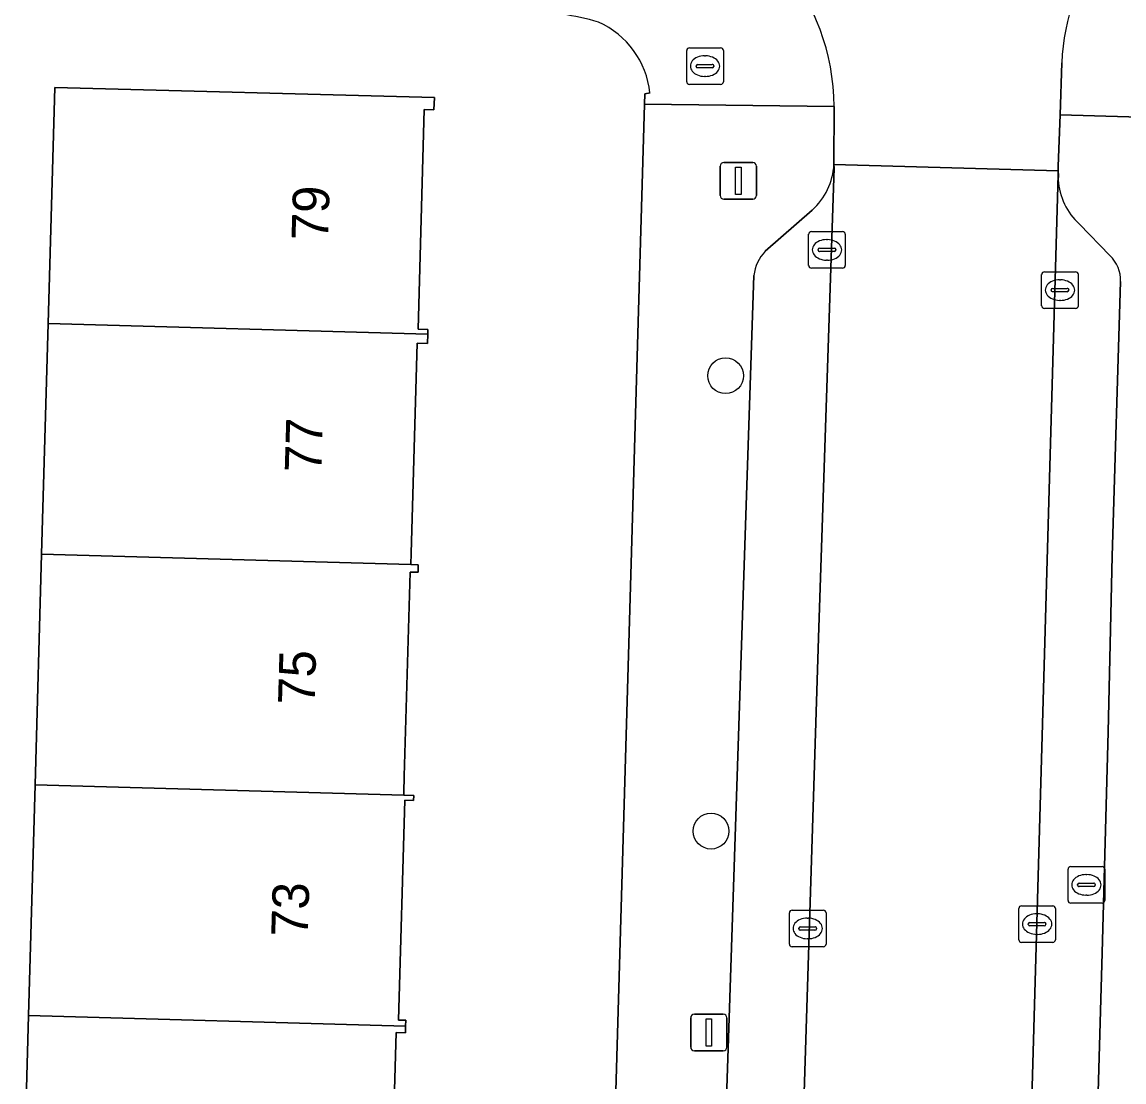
# Model space of a CAD drawing. Extents: x 162082 to 163401, y 388089 to 388636.
# Drawn here: x 162511.82 to 162541.91, y 388427.55 to 388456.49 of the extents above; entities that cross this region are included whole.
import ezdxf

# ---------------------------------------------------------------- set-up
doc = ezdxf.new("R2010")
doc.units = 0
for name, color, linetype in [('IMGEO_Boom', 7, 'Continuous'), ('IMGEO_Brandkraan', 7, 'Continuous'), ('IMGEO_Erf', 7, 'Continuous'), ('IMGEO_Kolk', 7, 'Continuous'), ('IMGEO_Lichtmast', 7, 'Continuous'), ('IMGEO_Pand', 7, 'Continuous'), ('IMGEO_Pand_nummerreeks', 7, 'Continuous'), ('IMGEO_Parkeervlak_open', 7, 'Continuous'), ('IMGEO_Rijbaan_lokaal_gesloten', 7, 'Continuous'), ('IMGEO_Rijbaan_lokaal_open', 7, 'Continuous'), ('IMGEO_Rioolput', 7, 'Continuous'), ('IMGEO_Voetpad_open', 7, 'Continuous')]:
    doc.layers.add(name, color=color, linetype=linetype)

msp = doc.modelspace()

# ---------------------------------------------------------------- linework, layer by layer
at = {"layer": 'IMGEO_Boom'}
for centre in [(162531.033, 388446.831), (162530.634, 388434.396)]:
    msp.add_circle(centre, 0.489, dxfattribs=at)
at = {"layer": 'IMGEO_Brandkraan'}
for p, q in [((162529.97, 388454.857), (162529.97, 388455.709)), ((162530.045, 388455.783), (162530.897, 388455.783)), ((162530.971, 388455.709), (162530.971, 388454.857)), ((162530.458, 388455.563), (162530.483, 388455.563)), ((162530.229, 388455.277), (162530.229, 388455.289)), ((162530.667, 388455.24), (162530.269, 388455.24)), ((162530.272, 388455.326), (162530.67, 388455.326)), ((162530.713, 388455.289), (162530.713, 388455.277)), ((162530.481, 388455.003), (162530.456, 388455.003)), ((162530.897, 388454.783), (162530.045, 388454.783))]:
    msp.add_line(p, q, dxfattribs=at)
for points in [[(162529.97, 388454.857), (162529.97, 388455.709)], [(162530.045, 388455.783), (162530.897, 388455.783)], [(162530.971, 388455.709), (162530.971, 388454.857)], [(162530.897, 388454.783), (162530.045, 388454.783)]]:
    msp.add_lwpolyline(points, dxfattribs=at)
for centre, radius, start, end in [((162530.047, 388455.707), 0.0765, 91.552, 178.448), ((162530.047, 388455.707), 0.0765, 91.552, 178.448), ((162530.895, 388455.707), 0.0765, 1.552, 88.448), ((162530.895, 388455.707), 0.0765, 1.552, 88.448), ((162530.269, 388455.286), 0.0403, 85.8775, 175.7526), ((162530.266, 388455.276), 0.0366, 178.938, 274.7102), ((162530.67, 388455.283), 0.043, 264.8664, 352.4533), ((162530.674, 388455.288), 0.0386, 1.7309, 96.639), ((162530.047, 388454.859), 0.0765, 181.552, 268.448), ((162530.047, 388454.859), 0.0765, 181.552, 268.448), ((162530.895, 388454.859), 0.0765, 271.552, 358.448), ((162530.895, 388454.859), 0.0765, 271.552, 358.448)]:
    msp.add_arc(centre, radius, start, end, dxfattribs=at)
for centre, major_axis, ratio, start_param, end_param in [((162530.457, 388455.283), (-0.387, 0.002), 0.722429, 4.712389, 7.853982), ((162530.482, 388455.283), (-0.39, 0.002), 0.717154, 1.570796, 4.712389)]:
    msp.add_ellipse(centre, major_axis=major_axis, ratio=ratio, start_param=start_param, end_param=end_param, dxfattribs=at)
at = {"layer": 'IMGEO_Erf'}
for points in [[(162511.823, 388423.065), (162512.001, 388429.364), (162512.178, 388435.661), (162512.356, 388441.959), (162512.534, 388448.256), (162512.716, 388454.703), (162523.081, 388454.43), (162523.067, 388454.092), (162522.804, 388454.1), (162522.635, 388448.098), (162522.906, 388448.091), (162522.902, 388447.964), (162522.895, 388447.711), (162522.612, 388447.719), (162522.449, 388441.984), (162522.44, 388441.675), (162522.641, 388441.669), (162522.635, 388441.462), (162522.417, 388441.468), (162522.26, 388435.898), (162522.247, 388435.449), (162522.245, 388435.378), (162522.519, 388435.37), (162522.515, 388435.233), (162522.27, 388435.24), (162522.101, 388429.237), (162522.301, 388429.232), (162522.297, 388429.074), (162522.292, 388428.886), (162522.034, 388428.894), (162521.865, 388422.918)], [(162527.34, 388403.481), (162528.815, 388454.241), (162528.823, 388454.524), (162528.969, 388454.551)]]:
    msp.add_lwpolyline(points, dxfattribs=at)
for centre, radius, start, end in [((162525.484, 388449.188), 7.589, 74.1247, 89.3819), ((162526.569, 388454.285), 2.414, 6.3175, 65.776)]:
    msp.add_arc(centre, radius, start, end, dxfattribs=at)
at = {"layer": 'IMGEO_Kolk'}
for p, q in [((162533.3, 388449.84), (162533.3, 388450.692)), ((162533.375, 388450.766), (162534.227, 388450.766)), ((162534.301, 388450.692), (162534.301, 388449.84)), ((162533.602, 388450.309), (162534, 388450.309)), ((162533.788, 388450.546), (162533.813, 388450.546)), ((162533.559, 388450.26), (162533.559, 388450.272)), ((162533.997, 388450.223), (162533.599, 388450.223)), ((162533.811, 388449.986), (162533.786, 388449.986)), ((162534.043, 388450.272), (162534.043, 388450.26)), ((162534.227, 388449.766), (162533.375, 388449.766)), ((162539.662, 388448.742), (162539.662, 388449.594)), ((162539.737, 388449.668), (162540.589, 388449.668)), ((162540.15, 388449.448), (162540.175, 388449.448)), ((162540.663, 388449.594), (162540.663, 388448.742)), ((162539.921, 388449.162), (162539.921, 388449.174)), ((162540.359, 388449.125), (162539.961, 388449.125)), ((162539.964, 388449.211), (162540.362, 388449.211)), ((162540.405, 388449.174), (162540.405, 388449.162)), ((162540.173, 388448.888), (162540.148, 388448.888)), ((162540.589, 388448.668), (162539.737, 388448.668)), ((162532.849, 388432.238), (162533.701, 388432.238)), ((162539.037, 388431.431), (162539.037, 388432.283)), ((162539.112, 388432.357), (162539.964, 388432.357)), ((162540.038, 388432.283), (162540.038, 388431.431)), ((162532.774, 388431.312), (162532.774, 388432.164)), ((162533.262, 388432.018), (162533.287, 388432.018)), ((162533.775, 388432.164), (162533.775, 388431.312)), ((162539.525, 388432.137), (162539.55, 388432.137)), ((162533.033, 388431.732), (162533.033, 388431.744)), ((162533.471, 388431.695), (162533.073, 388431.695)), ((162533.076, 388431.781), (162533.474, 388431.781)), ((162533.517, 388431.744), (162533.517, 388431.732)), ((162539.296, 388431.851), (162539.296, 388431.863)), ((162539.734, 388431.814), (162539.336, 388431.814)), ((162539.339, 388431.9), (162539.737, 388431.9)), ((162539.78, 388431.863), (162539.78, 388431.851)), ((162533.285, 388431.458), (162533.26, 388431.458)), ((162539.964, 388431.357), (162539.112, 388431.357)), ((162539.548, 388431.577), (162539.523, 388431.577)), ((162533.701, 388431.238), (162532.849, 388431.238))]:
    msp.add_line(p, q, dxfattribs=at)
for points in [[(162533.3, 388449.84), (162533.3, 388450.692)], [(162533.375, 388450.766), (162534.227, 388450.766)], [(162534.301, 388450.692), (162534.301, 388449.84)], [(162534.227, 388449.766), (162533.375, 388449.766)], [(162539.662, 388448.742), (162539.662, 388449.594)], [(162539.737, 388449.668), (162540.589, 388449.668)], [(162540.663, 388449.594), (162540.663, 388448.742)], [(162540.589, 388448.668), (162539.737, 388448.668)], [(162532.849, 388432.238), (162533.701, 388432.238)], [(162539.037, 388431.431), (162539.037, 388432.283)], [(162539.112, 388432.357), (162539.964, 388432.357)], [(162540.038, 388432.283), (162540.038, 388431.431)], [(162532.774, 388431.312), (162532.774, 388432.164)], [(162533.775, 388432.164), (162533.775, 388431.312)], [(162539.964, 388431.357), (162539.112, 388431.357)], [(162533.701, 388431.238), (162532.849, 388431.238)]]:
    msp.add_lwpolyline(points, dxfattribs=at)
for centre, radius, start, end in [((162533.377, 388450.69), 0.0765, 91.552, 178.448), ((162533.377, 388450.69), 0.0765, 91.552, 178.448), ((162534.225, 388450.69), 0.0765, 1.552, 88.448), ((162534.225, 388450.69), 0.0765, 1.552, 88.448), ((162533.599, 388450.269), 0.0403, 85.8775, 175.7526), ((162534.004, 388450.271), 0.0386, 1.7309, 96.639), ((162533.596, 388450.259), 0.0366, 178.938, 274.7102), ((162534, 388450.266), 0.043, 264.8664, 352.4533), ((162533.377, 388449.842), 0.0765, 181.552, 268.448), ((162533.377, 388449.842), 0.0765, 181.552, 268.448), ((162534.225, 388449.842), 0.0765, 271.552, 358.448), ((162534.225, 388449.842), 0.0765, 271.552, 358.448), ((162539.739, 388449.592), 0.0765, 91.552, 178.448), ((162539.739, 388449.592), 0.0765, 91.552, 178.448), ((162540.587, 388449.592), 0.0765, 1.552, 88.448), ((162540.587, 388449.592), 0.0765, 1.552, 88.448), ((162539.961, 388449.171), 0.0403, 85.8775, 175.7526), ((162539.958, 388449.161), 0.0366, 178.938, 274.7102), ((162540.362, 388449.168), 0.043, 264.8664, 352.4533), ((162540.366, 388449.173), 0.0386, 1.7309, 96.639), ((162539.739, 388448.744), 0.0765, 181.552, 268.448), ((162539.739, 388448.744), 0.0765, 181.552, 268.448), ((162540.587, 388448.744), 0.0765, 271.552, 358.448), ((162540.587, 388448.744), 0.0765, 271.552, 358.448), ((162532.851, 388432.162), 0.0765, 91.552, 178.448), ((162532.851, 388432.162), 0.0765, 91.552, 178.448), ((162533.699, 388432.162), 0.0765, 1.552, 88.448), ((162533.699, 388432.162), 0.0765, 1.552, 88.448), ((162539.114, 388432.281), 0.0765, 91.552, 178.448), ((162539.114, 388432.281), 0.0765, 91.552, 178.448), ((162539.962, 388432.281), 0.0765, 1.552, 88.448), ((162539.962, 388432.281), 0.0765, 1.552, 88.448), ((162533.073, 388431.741), 0.0403, 85.8775, 175.7526), ((162533.07, 388431.731), 0.0366, 178.938, 274.7102), ((162533.474, 388431.738), 0.043, 264.8664, 352.4533), ((162533.478, 388431.743), 0.0386, 1.7309, 96.639), ((162539.336, 388431.86), 0.0403, 85.8775, 175.7526), ((162539.333, 388431.85), 0.0366, 178.938, 274.7102), ((162539.737, 388431.857), 0.043, 264.8664, 352.4533), ((162539.741, 388431.862), 0.0386, 1.7309, 96.639), ((162539.114, 388431.433), 0.0765, 181.552, 268.448), ((162539.114, 388431.433), 0.0765, 181.552, 268.448), ((162539.962, 388431.433), 0.0765, 271.552, 358.448), ((162539.962, 388431.433), 0.0765, 271.552, 358.448), ((162532.851, 388431.314), 0.0765, 181.552, 268.448), ((162532.851, 388431.314), 0.0765, 181.552, 268.448), ((162533.699, 388431.314), 0.0765, 271.552, 358.448), ((162533.699, 388431.314), 0.0765, 271.552, 358.448)]:
    msp.add_arc(centre, radius, start, end, dxfattribs=at)
for centre, major_axis, ratio, start_param, end_param in [((162533.787, 388450.266), (-0.387, 0.002), 0.722429, 4.712389, 7.853982), ((162533.812, 388450.266), (-0.39, 0.002), 0.717154, 1.570796, 4.712389), ((162540.149, 388449.168), (-0.387, 0.002), 0.722429, 4.712389, 7.853982), ((162540.174, 388449.168), (-0.39, 0.002), 0.717154, 1.570796, 4.712389), ((162533.261, 388431.738), (-0.387, 0.002), 0.722429, 4.712389, 7.853982), ((162533.286, 388431.738), (-0.39, 0.002), 0.717154, 1.570796, 4.712389), ((162539.524, 388431.857), (-0.387, 0.002), 0.722429, 4.712389, 7.853982), ((162539.549, 388431.857), (-0.39, 0.002), 0.717154, 1.570796, 4.712389)]:
    msp.add_ellipse(centre, major_axis=major_axis, ratio=ratio, start_param=start_param, end_param=end_param, dxfattribs=at)
at = {"layer": 'IMGEO_Lichtmast'}
for p, q in [((162530.883, 388451.753), (162530.883, 388452.553)), ((162530.883, 388452.553), (162530.883, 388451.753)), ((162530.983, 388452.653), (162531.773, 388452.653)), ((162531.773, 388452.653), (162530.983, 388452.653)), ((162531.873, 388452.553), (162531.873, 388451.753)), ((162531.873, 388451.753), (162531.873, 388452.553)), ((162531.773, 388451.653), (162530.983, 388451.653)), ((162530.983, 388451.653), (162531.773, 388451.653)), ((162530.079, 388428.496), (162530.079, 388429.296)), ((162530.079, 388429.296), (162530.079, 388428.496)), ((162530.179, 388429.396), (162530.969, 388429.396)), ((162530.969, 388429.396), (162530.179, 388429.396)), ((162531.069, 388429.296), (162531.069, 388428.496)), ((162531.069, 388428.496), (162531.069, 388429.296)), ((162530.969, 388428.396), (162530.179, 388428.396)), ((162530.179, 388428.396), (162530.969, 388428.396))]:
    msp.add_line(p, q, dxfattribs=at)
for points in [[(162531.303, 388452.528), (162531.453, 388452.528), (162531.453, 388451.778), (162531.303, 388451.778), (162531.303, 388452.528)], [(162530.499, 388429.271), (162530.649, 388429.271), (162530.649, 388428.521), (162530.499, 388428.521), (162530.499, 388429.271)]]:
    msp.add_lwpolyline(points, dxfattribs=at)
for centre, start, end in [((162530.983, 388452.553), 90, 180), ((162530.983, 388452.553), 90, 180), ((162531.773, 388452.553), 0, 90), ((162531.773, 388452.553), 360, 90), ((162530.983, 388451.753), 180, 270), ((162530.983, 388451.753), 180, 270), ((162531.773, 388451.753), 270, 0), ((162531.773, 388451.753), 270, 0), ((162530.179, 388429.296), 90, 180), ((162530.179, 388429.296), 90, 180), ((162530.969, 388429.296), 0, 90), ((162530.969, 388429.296), 360, 90), ((162530.179, 388428.496), 180, 270), ((162530.179, 388428.496), 180, 270), ((162530.969, 388428.496), 270, 0), ((162530.969, 388428.496), 270, 0)]:
    msp.add_arc(centre, 0.1, start, end, dxfattribs=at)
at = {"layer": 'IMGEO_Pand'}
for points in [[(162522.902, 388447.964), (162522.906, 388448.091), (162522.635, 388448.098), (162522.804, 388454.1), (162523.067, 388454.092), (162523.081, 388454.43), (162512.716, 388454.703), (162512.534, 388448.256)], [(162522.612, 388447.719), (162522.895, 388447.711), (162522.902, 388447.964), (162512.534, 388448.256), (162512.356, 388441.959), (162522.44, 388441.675), (162522.449, 388441.984)], [(162522.417, 388441.468), (162522.635, 388441.462), (162522.641, 388441.669), (162522.44, 388441.675), (162512.356, 388441.959), (162512.178, 388435.661), (162522.245, 388435.378), (162522.247, 388435.449), (162522.26, 388435.898)], [(162522.27, 388435.24), (162522.515, 388435.233), (162522.519, 388435.37), (162522.245, 388435.378), (162512.178, 388435.661), (162512.001, 388429.364), (162522.297, 388429.074), (162522.301, 388429.232), (162522.101, 388429.237)], [(162511.823, 388423.065), (162522.057, 388422.777), (162522.059, 388422.915), (162521.865, 388422.918), (162522.034, 388428.894), (162522.292, 388428.886), (162522.297, 388429.074), (162512.001, 388429.364)]]:
    msp.add_lwpolyline(points, close=True, dxfattribs=at)
at = {"layer": 'IMGEO_Parkeervlak_open'}
for points in [[(162533.582, 388439.957), (162533.993, 388452.5), (162533.992, 388452.596)], [(162540.115, 388452.177), (162540.122, 388452.29), (162540.111, 388452.423), (162540.115, 388452.32), (162539.88, 388444.029), (162538.003, 388378.193)], [(162533.396, 388451.349), (162532.117, 388450.227)], [(162541.525, 388450.111), (162540.692, 388450.971)], [(162531.806, 388449.567), (162531.474, 388439.742), (162530.371, 388406.467)], [(162540.972, 388419.031), (162541.31, 388431.075), (162541.48, 388437.107), (162541.585, 388441.903), (162541.813, 388449.404)], [(162532.431, 388403.592), (162533.582, 388439.957)]]:
    msp.add_lwpolyline(points, dxfattribs=at)
for centre, radius, start, end in [((162532.173, 388452.699), 1.822, 312.1608, 356.7485), ((162541.881, 388452.281), 1.769, 183.3624, 227.7743), ((162532.933, 388449.439), 1.135, 136.0136, 173.5257), ((162540.91, 388449.448), 0.904, 357.1993, 47.1282)]:
    msp.add_arc(centre, radius, start, end, dxfattribs=at)
at = {"layer": 'IMGEO_Rijbaan_lokaal_gesloten'}
msp.add_lwpolyline([(162533.998, 388454.185), (162533.992, 388452.596), (162540.111, 388452.423), (162540.116, 388452.553), (162540.163, 388453.955), (162540.211, 388455.375)], dxfattribs=at)
for centre, radius, start, end in [((162527.766, 388454.121), 6.232, 0.5848, 78.2643), ((162546.194, 388455.112), 5.988, 142.6998, 177.4844)]:
    msp.add_arc(centre, radius, start, end, dxfattribs=at)
at = {"layer": 'IMGEO_Rijbaan_lokaal_open'}
msp.add_lwpolyline([(162539.88, 388444.029), (162540.115, 388452.32), (162540.111, 388452.423), (162533.992, 388452.596), (162533.993, 388452.5), (162533.582, 388439.957), (162532.431, 388403.592), (162532.305, 388399.384), (162531.679, 388378.011), (162531.665, 388377.549), (162537.986, 388377.403), (162538.003, 388378.193)], close=True, dxfattribs=at)
at = {"layer": 'IMGEO_Rioolput'}
for p, q in [((162540.458, 388433.429), (162541.31, 388433.429)), ((162540.383, 388432.503), (162540.383, 388433.355)), ((162540.871, 388433.209), (162540.896, 388433.209)), ((162541.384, 388433.355), (162541.384, 388432.503)), ((162540.642, 388432.923), (162540.642, 388432.935)), ((162541.08, 388432.886), (162540.682, 388432.886)), ((162540.685, 388432.972), (162541.083, 388432.972)), ((162541.126, 388432.935), (162541.126, 388432.923)), ((162540.894, 388432.649), (162540.869, 388432.649)), ((162541.31, 388432.429), (162540.458, 388432.429))]:
    msp.add_line(p, q, dxfattribs=at)
for points in [[(162540.458, 388433.429), (162541.31, 388433.429)], [(162540.383, 388432.503), (162540.383, 388433.355)], [(162541.384, 388433.355), (162541.384, 388432.503)], [(162541.31, 388432.429), (162540.458, 388432.429)]]:
    msp.add_lwpolyline(points, dxfattribs=at)
for centre, radius, start, end in [((162540.46, 388433.353), 0.0765, 91.552, 178.448), ((162540.46, 388433.353), 0.0765, 91.552, 178.448), ((162541.308, 388433.353), 0.0765, 1.552, 88.448), ((162541.308, 388433.353), 0.0765, 1.552, 88.448), ((162540.682, 388432.932), 0.0403, 85.8775, 175.7526), ((162540.679, 388432.922), 0.0366, 178.938, 274.7102), ((162541.083, 388432.929), 0.043, 264.8664, 352.4533), ((162541.087, 388432.934), 0.0386, 1.7309, 96.639), ((162540.46, 388432.505), 0.0765, 181.552, 268.448), ((162540.46, 388432.505), 0.0765, 181.552, 268.448), ((162541.308, 388432.505), 0.0765, 271.552, 358.448), ((162541.308, 388432.505), 0.0765, 271.552, 358.448)]:
    msp.add_arc(centre, radius, start, end, dxfattribs=at)
for centre, major_axis, ratio, start_param, end_param in [((162540.87, 388432.929), (-0.387, 0.002), 0.722429, 4.712389, 7.853982), ((162540.895, 388432.929), (-0.39, 0.002), 0.717154, 1.570796, 4.712389)]:
    msp.add_ellipse(centre, major_axis=major_axis, ratio=ratio, start_param=start_param, end_param=end_param, dxfattribs=at)
at = {"layer": 'IMGEO_Voetpad_open'}
for points in [[(162540.211, 388455.375), (162540.163, 388453.955), (162544.543, 388453.83), (162544.566, 388454.63)], [(162528.969, 388454.551), (162528.823, 388454.524), (162528.815, 388454.241), (162533.998, 388454.185)], [(162533.992, 388452.596), (162533.998, 388454.185), (162528.815, 388454.241), (162527.34, 388403.481), (162527.255, 388399.633), (162526.307, 388370.528), (162525.301, 388328.836), (162525.177, 388324.075)], [(162544.069, 388437.261), (162543.984, 388437.264), (162544.093, 388440.135), (162544.152, 388440.133), (162544.543, 388453.83), (162540.163, 388453.955), (162540.116, 388452.553), (162540.111, 388452.423), (162540.122, 388452.29), (162540.115, 388452.177)], [(162532.117, 388450.227), (162533.396, 388451.349)], [(162540.692, 388450.971), (162541.525, 388450.111)], [(162530.371, 388406.467), (162531.474, 388439.742), (162531.806, 388449.567)], [(162541.813, 388449.404), (162541.585, 388441.903), (162541.48, 388437.107), (162541.31, 388431.075), (162540.972, 388419.031), (162540.802, 388412.996), (162540.45, 388400.456), (162540.28, 388394.422), (162539.883, 388381.489), (162539.856, 388380.761)]]:
    msp.add_lwpolyline(points, dxfattribs=at)
for centre, radius, start, end in [((162527.766, 388454.121), 6.232, 0.5848, 78.2643), ((162546.194, 388455.112), 5.988, 142.6998, 177.4844), ((162525.484, 388449.188), 7.589, 74.1247, 89.3819), ((162526.569, 388454.285), 2.414, 6.3175, 65.776), ((162532.173, 388452.699), 1.822, 312.1608, 356.7485), ((162541.881, 388452.281), 1.769, 183.3624, 227.7743), ((162532.933, 388449.439), 1.135, 136.0136, 173.5257), ((162540.91, 388449.448), 0.904, 357.1993, 47.1282)]:
    msp.add_arc(centre, radius, start, end, dxfattribs=at)

# ---------------------------------------------------------------- texts
at = {"layer": 'IMGEO_Pand_nummerreeks'}
for s, rotation, p in [('79', 88.3328, (162520.179, 388450.516)), ('77', 88.3329, (162519.994, 388444.177)), ('75', 88.3329, (162519.81, 388437.838)), ('73', 88.3329, (162519.625, 388431.499))]:
    msp.add_text(s, height=1, rotation=rotation, dxfattribs=at).set_placement(p)

doc.saveas('drawing.dxf')
